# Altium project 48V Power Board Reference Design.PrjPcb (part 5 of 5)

## Sheet 48V E-Fuse.SchDoc
size 431 x 279 mm; Date: Not shown in title block; ApprovedBy: Not shown in title block; CheckedBy: Not shown in title block; Author: Not shown in title block; CompanyName: Not shown in title block; Engineer: Not shown in title block; Organization: Not shown in title block; Address1: Not shown in title block; Address2: Not shown in title block; Address3: Not shown in title block; Address4: Not shown in title block; DocumentNumber: 7; Revision: Use project parameter SCH_Rev; SheetNumber: 5; SheetTotal: 15; PageSetup: Record=PageOptions¦CenterHorizontal=True¦CenterVertical=True¦PrintScale=1.00¦XCorrection=1.00¦YCorrection=1.00¦PrintKind=0¦BorderSize=5000000¦LeftOffset=0¦BottomOffset=0¦Orientation=2¦PaperLength=1000¦PaperWidth=1000¦Scale=100¦PaperSource=15¦PrintQuality=600¦MediaType=1¦DitherType=10¦PaperKind=Letter¦PrintScaleMode=1
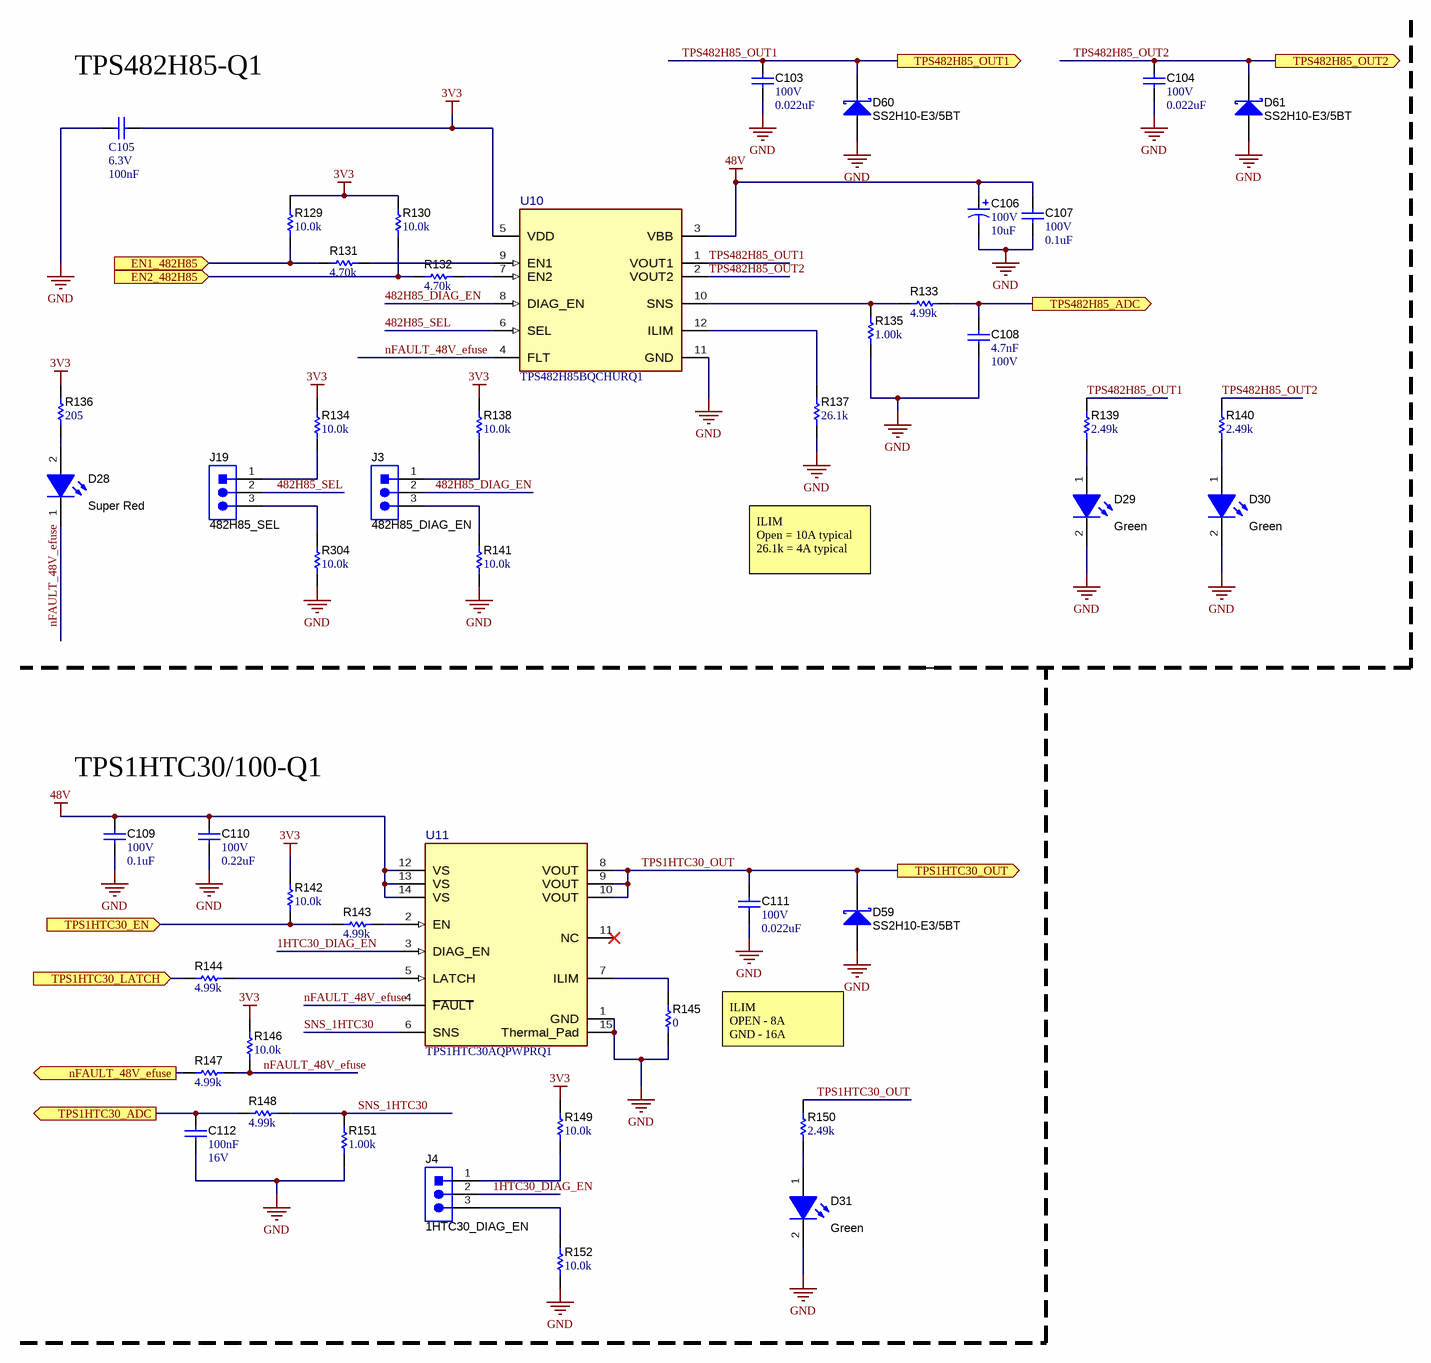
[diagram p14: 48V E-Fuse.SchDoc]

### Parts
C103  VDC_V: 100V  ValueDisplayed: 0.022uF  [1206]  (hidden comment: 12061C223JAT2A)
C104  VDC_V: 100V  ValueDisplayed: 0.022uF  [1206]  (hidden comment: 12061C223JAT2A)
C105  Cap_F: 100nF  Rated Voltage (DC): 6.3V  [WCAP-CSGP_0402_L1W0.5H0.5]  (hidden comment: 885012105001)
C106  VDC_V: 100V  ValueDisplayed: 10uF  [SM_RADIAL_E]  (hidden comment: EEE-2AA100UP)
C107  VDC_V: 100V  ValueDisplayed: 0.1uF  [1206_180]  (hidden comment: C3216X7R2A104K160AA)
C108  Cap_F: 4.7nF  VDC_V: 100V  [0603]  (hidden comment: GCM188R72A472KA37D)
C109  VDC_V: 100V  ValueDisplayed: 0.1uF  [1206]  (hidden comment: GRM319R72A104KA01D)
C110  VDC_V: 100V  ValueDisplayed: 0.22uF  [1206]  (hidden comment: C3216X7R2A224K115AA)
C111  VDC_V: 100V  ValueDisplayed: 0.022uF  [1206]  (hidden comment: 12061C223JAT2A)
C112  Cap_F: 100nF  VDC_V: 16V  [0603]  (hidden comment: GCM188R71C104KA37J)
D28  value Super Red  [WL-SMCW_RED]  (hidden comment: 150060SS75000)
D29  value Green  [LTST-C191_Green]  (hidden comment: LTST-C191KGKT)
D30  value Green  [LTST-C191_Green]  (hidden comment: LTST-C191KGKT)
D31  value Green  [LTST-C191_Green]  (hidden comment: LTST-C191KGKT)
D59  SS2H10-E3/5BT  [SMB]
D60  SS2H10-E3/5BT  [SMB]
D61  SS2H10-E3/5BT  [SMB]
J3  482H85_DIAG_EN  [TSW-103-07-G-S]
J4  1HTC30_DIAG_EN  [TSW-103-07-G-S]
J19  482H85_SEL  [TSW-103-07-G-S]
R129  ValueDisplayed: 10.0k  [0603]  (hidden comment: RNCF0603TKY10K0)
R130  ValueDisplayed: 10.0k  [0603]  (hidden comment: RNCF0603TKY10K0)
R131  ValueDisplayed: 4.70k  [0603]  (hidden comment: RC0603FR-074K7L)
R132  ValueDisplayed: 4.70k  [0603]  (hidden comment: RC0603FR-074K7L)
R133  ValueDisplayed: 4.99k  [0603]  (hidden comment: CRCW06034K99FKEAC)
R134  ValueDisplayed: 10.0k  [0603]  (hidden comment: RNCF0603TKY10K0)
R135  ValueDisplayed: 1.00k  [0603]  (hidden comment: ERA3AEB102V)
R136  ValueDisplayed: 205  [0603]  (hidden comment: RC0603FR-07205RL)
R137  ValueDisplayed: 26.1k  [0603]  (hidden comment: RC0603FR-0726K1L)
R138  ValueDisplayed: 10.0k  [0603]  (hidden comment: RNCF0603TKY10K0)
R139  ValueDisplayed: 2.49k  [0603]  (hidden comment: RC0603FR-072K49L)
R140  ValueDisplayed: 2.49k  [0603]  (hidden comment: RC0603FR-072K49L)
R141  ValueDisplayed: 10.0k  [0603]  (hidden comment: RNCF0603TKY10K0)
R142  ValueDisplayed: 10.0k  [0603]  (hidden comment: RNCF0603TKY10K0)
R143  ValueDisplayed: 4.99k  [0603]  (hidden comment: CRCW06034K99FKEAC)
R144  ValueDisplayed: 4.99k  [0603]  (hidden comment: CRCW06034K99FKEAC)
R145  ValueDisplayed: 0  [0603]  (hidden comment: ERJ-3GEY0R00V)
R146  ValueDisplayed: 10.0k  [0603]  (hidden comment: ERJ-3EKF1002V)
R147  ValueDisplayed: 4.99k  [0603]  (hidden comment: CRCW06034K99FKEAC)
R148  ValueDisplayed: 4.99k  [0603]  (hidden comment: CRCW06034K99FKEAC)
R149  ValueDisplayed: 10.0k  [0603]  (hidden comment: RNCF0603TKY10K0)
R150  ValueDisplayed: 2.49k  [0603]  (hidden comment: RC0603FR-072K49L)
R151  ValueDisplayed: 1.00k  [0603]  (hidden comment: ERJ-3EKF1001V)
R152  ValueDisplayed: 10.0k  [0603]  (hidden comment: RNCF0603TKY10K0)
R304  ValueDisplayed: 10.0k  [0603]  (hidden comment: RNCF0603TKY10K0)
U10  TPS482H85BQCHURQ1  [CHU0012A-MFG]
U11  TPS1HTC30AQPWPRQ1  [PWP0014C-MFG]

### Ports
EN1_482H85 (in), EN2_482H85 (in), nFAULT_48V_efuse (out), TPS1HTC30_ADC (out), TPS1HTC30_EN (in), TPS1HTC30_LATCH (in), TPS1HTC30_OUT (out), TPS482H85_ADC (out), TPS482H85_OUT1 (out), TPS482H85_OUT2 (out)

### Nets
3V3: C105.1 R129.2 R130.2 R134.2 R136.2 R138.2 R142.2 R146.2 R149.2 U10.5(VDD)
48V: C106.1(+) C107.1 C109.1 C110.1 U10.3(VBB) U11.12(VS) U11.13(VS) U11.14(VS)
GND: C103.2 C104.2 C105.2 C106.2(-) C107.2 C108.2 C109.2 C110.2 C111.2 C112.2 D29.2(K) D30.2(K) D31.2(K) D59.2(A) D60.2(A) D61.2(A) R135.1 R137.1 R141.1 R145.1 R151.1 R152.1 R304.1 U10.11(GND) U11.1(GND) U11.15(Thermal_Pad)
1HTC30_DIAG_EN: J4.2 U11.3(DIAG_EN)  [project net 1HTC30_DIAG_EN_5]
482H85_DIAG_EN: J3.2 U10.8(DIAG_EN)  [project net 482H85_DIAG_EN_5]
482H85_SEL: J19.2 U10.6(SEL)  [project net 482H85_SEL_5]
EN1_482H85: R129.1 R131.1 ; port EN1_482H85
EN2_482H85: R130.1 R132.1 ; port EN2_482H85
nFAULT_48V_efuse: R147.1 ; port nFAULT_48V_efuse
nFAULT_48V_efuse: D28.1(K) R146.1 R147.2 U10.4(FLT) U11.4(~{FAULT})  [project net nFAULT_48V_efuse_5]  [a separate net that carries the same name]
SNS_1HTC30: R148.2 R151.2 U11.6(SNS)  [project net SNS_1HTC30_5]
TPS1HTC30_ADC: C112.1 R148.1 ; port TPS1HTC30_ADC
TPS1HTC30_EN: R142.1 R143.1 ; port TPS1HTC30_EN
TPS1HTC30_LATCH: R144.1 ; port TPS1HTC30_LATCH
TPS1HTC30_OUT: C111.1 D59.1(K) R150.2 U11.8(VOUT) U11.9(VOUT) U11.10(VOUT) ; port TPS1HTC30_OUT
TPS482H85_ADC: C108.1 R133.2 ; port TPS482H85_ADC
TPS482H85_OUT1: C103.1 D60.1(K) R139.2 U10.1(VOUT1) ; port TPS482H85_OUT1
TPS482H85_OUT2: C104.1 D61.1(K) R140.2 U10.2(VOUT2) ; port TPS482H85_OUT2
NetD28_2: D28.2(A) R136.1
NetD29_1: D29.1(A) R139.1
NetD30_1: D30.1(A) R140.1
NetD31_1: D31.1(A) R150.1
NetJ3_1: J3.1 R138.1
NetJ3_3: J3.3 R141.2
NetJ4_1: J4.1 R149.1
NetJ4_3: J4.3 R152.2
NetJ19_1: J19.1 R134.1
NetJ19_3: J19.3 R304.2
NetR131_2: R131.2 U10.9(EN1)
NetR132_2: R132.2 U10.7(EN2)
NetR133_1: R133.1 R135.2 U10.10(SNS)
NetR137_2: R137.2 U10.12(ILIM)
NetR143_2: R143.2 U11.2(EN)
NetR144_2: R144.2 U11.5(LATCH)
NetR145_2: R145.2 U11.7(ILIM)

Not connected (* = marked no-connect by the designer): U11 11(NC)*

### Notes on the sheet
- (near C105) TPS482H85-Q1
- ILIM
  Open = 10A typical
  26.1k = 4A typical
- TPS1HTC30/100-Q1
- ILIM
  OPEN - 8A
  GND - 16A

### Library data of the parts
C103 C104 C111 = CMP-0008495-2: CAP, CERM, 0.022 uF, 100 V, +/- 5%, X7R, 1206; Manufacturer: AVX; TaMin_C: -55°C; ESR_ohm: 79m; Polarized: N; SizeAreaWB_mm2: 10.92; Value1: 0.079 ohm; U/M: EA; TaMax_C: 125°C; SizeZ_mm: 1.35; SizeX_mm: 3.2; SizeY_mm: 1.6; SizeArea_mm2: 5.12; Cap_F: 22nF; AEC Category: Q200
C105 = CMP-0115207-1: WCAP-CSGP Multilayer Ceramic Chip Capacitor, General Purpose, size 0402, X5R, 100nF, 6.3VDC; Manufacturer: Wurth Elektronik; Capacitance Tolerance: +/-20%; Dissipation Factor: 10%; Insulation Resistance: 1GOhm; Technical Reference: X5R0402104M6R3DFCT10000
C106 = CMP-0011164-2: CAP, AL, 10 uF, 100 V, +/- 20%, AEC-Q200 Grade 3, SMD; Manufacturer: Panasonic; TaMin_C: -40°C; Polarized: Y; SizeAreaWB_mm2: 118.45; Value1: Unknown; U/M: EA; Value: 10uF; TaMax_C: 85°C; SizeZ_mm: 6.2; SizeX_mm: 9.5; SizeY_mm: 8.3; Cap_Case: 8.0x6.0mm; SizeArea_mm2: 78.85; CompType: Capacitor; Cap_F: 10µF; IRMS_A: 50mA; AEC Grade: 3; AEC Category: Q200
C107 = CMP-0008709-1: CAP, CERM, 0.1 uF, 100 V, +/- 10%, X7R, 1206; Manufacturer: TDK; TaMin_C: -55°C; ESR_ohm: 0.030343; Polarized: N; SizeAreaWB_mm2: 10.92; Value1: 0.030343 ohm; U/M: EA; Value: 0.1uF; TaMax_C: 125°C; SizeZ_mm: 1.8; SizeX_mm: 3.2; SizeY_mm: 1.6; SizeArea_mm2: 5.12; Cap_F: 100nF; IRMS_A: 1.33802A; AEC Category: Q200
C108 = CMP-0079247-1: CAP, CERM, 4700 pF, 100 V,+/- 10%, X7R, AEC-Q200 Grade 1, 0603; Manufacturer: MuRata; SizeAreaWB_mm2: 4.68; SizeArea_mm2: 1.28; AEC Qualified: Y; AEC Category: Q200; Value: 4700pF; TaMax_C: 125°C; SizeZ_mm: 1; Polarized: N; TaMin_C: -55°C; SizeY_mm: 0.8; U/M: EA; SizeX_mm: 1.6
C109 = CMP-0008881-2: CAP, CERM, 0.1 uF, 100 V, +/- 10%, X7R, 1206; Manufacturer: MuRata; TaMin_C: -55°C; Polarized: N; SizeAreaWB_mm2: 10.92; Value1: Unknown; U/M: EA; Value: 0.1uF; TaMax_C: 125°C; SizeZ_mm: 1.35; SizeX_mm: 3.2; SizeY_mm: 1.6; SizeArea_mm2: 5.12; Cap_F: 100nF; AEC Category: Q200
C110 = CMP-0008713-2: CAP, CERM, 0.22 uF, 100 V, +/- 10%, X7R, 1206; Manufacturer: TDK; TaMin_C: -55°C; ESR_ohm: 14.93m; Polarized: N; SizeAreaWB_mm2: 10.92; Value1: 0.01493 ohm; U/M: EA; Value: 0.22uF; TaMax_C: 125°C; SizeZ_mm: 1.35; SizeX_mm: 3.2; SizeY_mm: 1.6; SizeArea_mm2: 5.12; Cap_F: 220nF; IRMS_A: 1.8906A; AEC Category: Q200
C112 = CMP-0007135-2: CAP, CERM, 0.1 uF, 16 V, +/- 10%, X7R, AEC-Q200 Grade 1, 0603; Manufacturer: MuRata; TaMin_C: -55°C; Polarized: N; SizeAreaWB_mm2: 4.68; Value1: Unknown; U/M: EA; Value: 0.1uF; TaMax_C: 125°C; SizeZ_mm: 1; SizeX_mm: 1.6; SizeY_mm: 0.8; SizeArea_mm2: 1.28; AEC Qualified: Y; AEC Category: Q200
D28 = CMP-0002893-1: LED, Super Red, SMD; Manufacturer: Wurth Elektronik; Io_A: 20mA; Value1: W; U/M: EA; Vf_V: 1.9V; Type: AlInGaP
D29-D31 = CMP-0078478-1: LED, Green, SMD; Manufacturer: Lite-On; Io_A: 30mA; Power_TotalModule: 75mW; Green_Lifecycle: Not Set; Vr_V: 5V; Tjmax_C: 85°C; Green_REACh: Incomplete; Value1: 0.075W; Angle: 130; Ir_A: 10µA; Vf_V: 2V; Type: AlInGaP
D59-D61 = CMP-0028987-2: Diode, Schottky, 100 V, 2 A, SMB; Manufacturer: Vishay-Semiconductor; Vf_V: 790mV; AEC Qualified: N; SizeArea_mm2: 21.336; Value: 100V; SizeX_mm: 5.6; Value1: 2A; Value2: 0.79V; SizeZ_mm: 2.6; SizeAreaWB_mm2: 44.156; AEC Category: Q101; TJmax_C: 175°C; SizeY_mm: 3.81
J3 J4 J19 = CMP-0075407-2: Header, 100mil, 3x1, Gold, TH; Manufacturer: Samtec; Pitch_mm: 2.54; Cert_VDE: N; Gender: Male; Cert_CSA: Y; Voltage_V: 550V; Green_REACh: Passed; Current_A: 6.3A; Green_Lifecycle: Active; Row_Count: 1
R129 R130 R134 R138 R141 R142 R149 R152 R304 = CMP-0023626-3: RES, 10.0 k, 0.01%, 0.063 W, 0603; Manufacturer: Stackpole Electronics Inc; Power_W: 63mW; TempCo: 5 ppm/C; Value_Code: 10k0; U/M: EA; Value: 10.0k; Res_ohm: 10k; SizeX_mm: 1.6; SizeY_mm: 0.8; SizeZ_mm: 1; Value2: 0.063W; SizeArea_mm2: 1.28; VDC_V: 50V; AEC Category: Q200
R131 R132 = CMP-0023153-5: RES, 4.70 k, 1%, 0.1 W, 0603; Manufacturer: Yageo; Power_W: 100mW; TempCo: 100 ppm/C; Value_Code: 4k70; Value: 4.70k; Res_ohm: 4.7k; SizeX_mm: 1.6; SizeY_mm: 0.8; SizeZ_mm: 1; Value2: 0.1W; SizeArea_mm2: 1.28; AEC Qualified: N; VDC_V: 75V; AEC Category: Q200; SizeAreaWB_mm2: 4.68
R133 R143 R144 R147 R148 = CMP-0082533-1: RES, 4.99 k, 1%, 0.1 W, 0603; Manufacturer: Vishay-Dale; Power_W: 100mW; TempCo: 100 ppm/C; SizeAreaWB_mm2: 4.68; Value_Code: 4k99; Value: 4.99k; EIA_Code: E96; SizeX_mm: 1.6; SizeY_mm: 0.8; SizeZ_mm: 1; Value2: 0.1W; SizeArea_mm2: 1.28; AEC Qualified: N; VDC_V: 75V; AEC Category: Q200
R135 = CMP-0078581-1: RES, 1.00 k, 0.1%, 0.1 W, AEC-Q200 Grade 0, 0603; Manufacturer: Panasonic; Power_W: 100mW; TempCo: 25 ppm/C; Value_Code: 1k00; Value: 1.00k; EIA_Code: E192; Res_ohm: 1k; SizeX_mm: 1.6; SizeY_mm: 0.8; SizeZ_mm: 1; Value2: 0.1W; SizeArea_mm2: 1.28; AEC Qualified: Y; AEC Grade: 0; AEC Category: Q200
R136 = CMP-0022904-5: RES, 205, 1%, 0.1 W, 0603; Manufacturer: Yageo; Power_W: 100mW; TempCo: 100 ppm/C; Value_Code: 205R; Value: 205; EIA_Code: E96; SizeX_mm: 1.6; SizeY_mm: 0.8; SizeZ_mm: 1; Value2: 0.1W; SizeArea_mm2: 1.28; AEC Qualified: N; VDC_V: 75V; AEC Category: Q200; SizeAreaWB_mm2: 4.68
R137 = CMP-0022957-5: RES, 26.1 k, 1%, 0.1 W, 0603; Manufacturer: Yageo; Power_W: 100mW; TempCo: 100 ppm/C; Value_Code: 26k1; Value: 26.1k; EIA_Code: E96; SizeX_mm: 1.6; SizeY_mm: 0.8; SizeZ_mm: 1; Value2: 0.1W; SizeArea_mm2: 1.28; AEC Qualified: N; VDC_V: 75V; AEC Category: Q200; SizeAreaWB_mm2: 4.68
R139 R140 R150 = CMP-0022990-5: RES, 2.49 k, 1%, 0.1 W, 0603; Manufacturer: Yageo; Power_W: 100mW; TempCo: 100 ppm/C; Value_Code: 2k49; Value: 2.49k; EIA_Code: E96; SizeX_mm: 1.6; SizeY_mm: 0.8; SizeZ_mm: 1; Value2: 0.1W; SizeArea_mm2: 1.28; AEC Qualified: N; VDC_V: 75V; AEC Category: Q200; SizeAreaWB_mm2: 4.68
R145 = CMP-0025874-4: RES, 0, 5%, 0.1 W, AEC-Q200 Grade 0, 0603; Manufacturer: Panasonic; Power_W: 100mW; TempCo: 600 ppm/C; Value_Code: 0000; Value: 0; EIA_Code: E24; SizeX_mm: 1.6; SizeY_mm: 0.8; SizeZ_mm: 1; Value2: 0.1W; SizeArea_mm2: 1.28; AEC Qualified: Y; VDC_V: 50V; AEC Category: Q200; SizeAreaWB_mm2: 4.68
R146 = CMP-0022684-2: RES, 10.0 k, 1%, 0.1 W, 0603; Manufacturer: Panasonic; Power_W: 100mW; TempCo: 100 ppm/C; Value_Code: 10k0; U/M: EA; Value: 10.0k; EIA_Code: E96; Res_ohm: 10k; SizeX_mm: 1.6; SizeY_mm: 0.8; SizeZ_mm: 1; Value2: 0.1W; SizeArea_mm2: 1.28; VDC_V: 75V; AEC Category: Q200
R151 = CMP-0022680-3: RES, 1.00 k, 1%, 0.1 W, 0603; Manufacturer: Panasonic; Power_W: 100mW; TempCo: 100 ppm/C; Value_Code: 1k00; U/M: EA; Value: 1.00k; EIA_Code: E96; Res_ohm: 1k; SizeX_mm: 1.6; SizeY_mm: 0.8; SizeZ_mm: 1; SizeArea_mm2: 1.28; VDC_V: 75V; AEC Category: Q200; Value2: 0.1W
U10 = CMP-0122244-1: 48-V, 85-mΩ Dual-Channel Smart High-Side Switch; Manufacturer: Texas Instruments; SizeZ_mm: 1mm; AEC Qualified: Yes; AEC Grade: Grade 1; Max Supply Voltage: 64V; Min Supply Voltage: 6V; Number Of Outputs: 2; Standoff Height: 0mm; TaMax_C: +125°C; TaMin_C: -40°C
U11 = CMP-0097835-1: 30-mΩ, 24-V, 6-A Single-Channel Automotive Smart High-Side Switch; Manufacturer: Texas Instruments; Min Supply Voltage: 6V; Number Of Outputs: 1; Nominal Supply Current: 0.98-1mA; TaMin_C: -40°C; TaMax_C: +125°C; SizeZ_mm: 1.2mm; AEC Grade: Grade 1; Max Supply Voltage: 48V; AEC Qualified: Yes; Standoff Height: 0.05mm

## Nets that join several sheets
3V3: LM74900-Q1 (R123.2 R124.2 R125.2), TPS1211-Q1 (R208.1 R210.1 R214.2 R215.2), TPS4HC120-Q1 (R97.2 R98.2 R104.2), TPS1214-Q1 (R35.2 R39.2 R40.2 R41.2), (BLDC) DRV8363-Q1 (5 pins), Motor Drivers (6 pins), 12V E-Fuse (9 pins), Backbone_input2 (5 pins), Power (R61.2), (SPI Expander) TXE8124-Q1 (5 pins), AM26 Connectors (J16.1), Backbone_input1 (8 pins), 48V E-Fuse (10 pins)
5V_AM26: Power (D12.1), AM26 Connectors (J17.2)
12V: LM74900-Q1 (14 pins), TPS1211-Q1 (9 pins), TPS4HC120-Q1 (C87.1 C88.1 R307.1 TP45.1), (BLDC) DRV8363-Q1 (C167.1 U16.30), Motor Drivers (7 pins), 12V E-Fuse (13 pins), Power (C70.1 D10.1 R57.2 U5.6)
48V: Top Sheet (J7.2), TPS1214-Q1 (10 pins), (BLDC) DRV8363-Q1 (23 pins), Motor Drivers (8 pins), Backbone_input2 (8 pins), Power (L4.1), Backbone_input1 (10 pins), 48V E-Fuse (8 pins)
GND: Top Sheet (10 pins), LM74900-Q1 (15 pins), TPS1211-Q1 (17 pins), TPS4HC120-Q1 (19 pins), TPS1214-Q1 (23 pins), (BLDC) DRV8363-Q1 (31 pins), Motor Drivers (45 pins), 12V E-Fuse (28 pins), Backbone_input2 (25 pins), Power (25 pins), (SPI Expander) TXE8124-Q1 (C199.2 U17.3), AM26 Connectors (6 pins), Backbone_input1 (29 pins), 48V E-Fuse (26 pins)
: (BLDC) DRV8363-Q1 (R258.1), Motor Drivers (R7.1 R17.1), 12V E-Fuse (R67.1 R86.1), (SPI Expander) TXE8124-Q1 (R294.1), AM26 Connectors (J15.80)
BUCK_PG: Power (R50.1 R61.1 U4.2 U5.1), (SPI Expander) TXE8124-Q1 (U17.22)
DIAGEN_TPS4HC120: TPS4HC120-Q1 (R94.2), (SPI Expander) TXE8124-Q1 (U17.10)
DRV8245_OUT1: Top Sheet (J8.2), Motor Drivers (C3.2 R2.2 U1.8 U1.9)
DRV8245_OUT2: Top Sheet (J8.1), Motor Drivers (C4.2 R1.2 U1.5 U1.6)
DRV8263_OUT1: Top Sheet (J9.2), Motor Drivers (C21.2 C22.1 R15.2 U2.7)
DRV8263_OUT2: Top Sheet (J9.1), Motor Drivers (C22.2 C24.2 R16.2 U2.5)
DRV8363_EBRAKE: (BLDC) DRV8363-Q1 (U16.29), (SPI Expander) TXE8124-Q1 (U17.19)
DRV8363_INHA: (BLDC) DRV8363-Q1 (U16.11), AM26 Connectors (J14.36)
DRV8363_INHB: (BLDC) DRV8363-Q1 (U16.13), AM26 Connectors (J14.34)
DRV8363_INHC: (BLDC) DRV8363-Q1 (U16.15), AM26 Connectors (J14.32)
DRV8363_INLA: (BLDC) DRV8363-Q1 (U16.12), AM26 Connectors (J14.37)
DRV8363_INLB: (BLDC) DRV8363-Q1 (U16.14), AM26 Connectors (J14.33)
DRV8363_INLC: (BLDC) DRV8363-Q1 (U16.16), AM26 Connectors (J14.31)
DRV8363_OUTA: Top Sheet (J5.1), (BLDC) DRV8363-Q1 (14 pins)
DRV8363_OUTB: Top Sheet (J5.2), (BLDC) DRV8363-Q1 (14 pins)
DRV8363_OUTC: Top Sheet (J5.3), (BLDC) DRV8363-Q1 (14 pins)
DRV8363_SOA: (BLDC) DRV8363-Q1 (C186.1 R278.1), AM26 Connectors (J13.23)
DRV8363_SOB: (BLDC) DRV8363-Q1 (C187.1 R279.1), AM26 Connectors (J13.28)
DRV8363_SOC: (BLDC) DRV8363-Q1 (C188.1 R280.1), AM26 Connectors (J13.26)
DRVOFF_DRV82xx: Motor Drivers (U1.10 U2.8), (SPI Expander) TXE8124-Q1 (U17.24)
DRVOFF_DRV8363: (BLDC) DRV8363-Q1 (U16.9), (SPI Expander) TXE8124-Q1 (U17.17)
EN1_482H85: (SPI Expander) TXE8124-Q1 (U17.12), 48V E-Fuse (R129.1 R131.1)
EN1_TPS4HC120: TPS4HC120-Q1 (R90.2), (SPI Expander) TXE8124-Q1 (U17.4)
EN2_482H85: (SPI Expander) TXE8124-Q1 (U17.13), 48V E-Fuse (R130.1 R132.1)
EN2_TPS4HC120: TPS4HC120-Q1 (R91.2), (SPI Expander) TXE8124-Q1 (U17.5)
EN3_TPS4HC120: TPS4HC120-Q1 (R92.2), (SPI Expander) TXE8124-Q1 (U17.6)
EN4_TPS4HC120: TPS4HC120-Q1 (R93.2), (SPI Expander) TXE8124-Q1 (U17.7)
EN/IN1_DRV8245: Motor Drivers (U1.11), AM26 Connectors (J14.40)
EN/IN1_DRV8263: Motor Drivers (U2.9), AM26 Connectors (J15.78)
EN_LM74900: LM74900-Q1 (R123.1 U9.6), AM26 Connectors (J18.44)
EN_TPS1214: TPS1214-Q1 (R35.1 U3.1), AM26 Connectors (J15.57)
FLT_I_TPS1211: TPS1211-Q1 (D41.1 R208.2 U14.5), AM26 Connectors (J18.43)
FLT_T_TPS1211: TPS1211-Q1 (D42.1 R210.2 U14.4), AM26 Connectors (J13.7)
IDIR_TPS1212_input1: AM26 Connectors (J15.51), Backbone_input1 (R181.1)
IDIR_TPS1212_input2: Backbone_input2 (R242.1), AM26 Connectors (J14.13)
IMON_LM74900: LM74900-Q1 (R126.2 U9.10), AM26 Connectors (J18.69)
IMON_TPS1211: TPS1211-Q1 (R211.2 TP22.1 U14.7), AM26 Connectors (J18.67)
IMON_TPS1212_input1: AM26 Connectors (J13.29), Backbone_input1 (5 pins)
IMON_TPS1212_input2: Backbone_input2 (C161.1 R252.2 TP28.1 U15.9), AM26 Connectors (J13.25)
IMON_TPS1214: TPS1214-Q1 (C57.1 R45.2 TP7.1 U3.9), AM26 Connectors (J13.24)
INP_G_TPS1211: TPS1211-Q1 (U14.2), AM26 Connectors (J14.15)
INP_TPS1211: TPS1211-Q1 (U14.3), AM26 Connectors (J14.14)
INP_TPS1212_input1: AM26 Connectors (J15.52), Backbone_input1 (R176.1 U13.4)
INP_TPS1212_input2: Backbone_input2 (R237.1), AM26 Connectors (J14.18)
INP_TPS1214: TPS1214-Q1 (U3.3), AM26 Connectors (J15.53)
IPROPI_DRV8245: Motor Drivers (C6.1 R5.2), AM26 Connectors (J18.63)
IPROPI_DRV8263: Motor Drivers (C25.1 R12.2), AM26 Connectors (J18.46)
ITMPO_TPS1212_input1: AM26 Connectors (J13.27), Backbone_input1 (C130.1 R188.2 U12.10)
ITMPO_TPS1212_input2: Backbone_input2 (C159.1 R249.2 U15.10), AM26 Connectors (J13.6)
ITMPO_TPS1214: TPS1214-Q1 (C56.1 R42.2 U3.10), AM26 Connectors (J13.2)
LHI_TPS2HCS05: 12V E-Fuse (R74.2), (SPI Expander) TXE8124-Q1 (U17.15)
LHI_TPS2HCS10: 12V E-Fuse (R80.2), (SPI Expander) TXE8124-Q1 (U17.26)
nCS_DRV8245: Motor Drivers (R6.2 R9.1), AM26 Connectors (J18.45)
nCS_DRV8263: Motor Drivers (R18.2 R20.1), AM26 Connectors (J18.50)
nCS_DRV8363: (BLDC) DRV8363-Q1 (R257.2 R260.1), AM26 Connectors (J18.49)
nCS_TPS2HCS05: 12V E-Fuse (R66.1 R72.1), AM26 Connectors (J13.9)
nCS_TPS2HCS10: 12V E-Fuse (R88.2 R89.1), AM26 Connectors (J14.19)
nCS_TXE8124: (SPI Expander) TXE8124-Q1 (R291.2 R296.1), AM26 Connectors (J15.71)
nFAULT_48V_efuse: AM26 Connectors (J14.38), 48V E-Fuse (R147.1)
nFAULT_1214: TPS1214-Q1 (D9.1 R40.1 U3.6), AM26 Connectors (J15.58)
nFAULT_DRV82xx: Motor Drivers (D3.1 R4.1 U1.1 U2.1), AM26 Connectors (J13.8)
nFAULT_DRV8363: (BLDC) DRV8363-Q1 (D50.1 R262.1 U16.22), (SPI Expander) TXE8124-Q1 (U17.16)
nFAULT_LM74900: LM74900-Q1 (R125.1 U9.12), AM26 Connectors (J18.48)
nFAULT_TPS4HC120: TPS4HC120-Q1 (R99.2), (SPI Expander) TXE8124-Q1 (U17.11)
nFLT_LM686x5: Power (R49.1 U4.8), (SPI Expander) TXE8124-Q1 (U17.14)
nFLT_TPS2HCS10/05: 12V E-Fuse (R84.1), (SPI Expander) TXE8124-Q1 (U17.25)
nFLT_TPS1212_input1: AM26 Connectors (J15.73), Backbone_input1 (R185.2)
nFLT_TPS1212_input2: Backbone_input2 (R246.2), AM26 Connectors (J14.12)
nINT_TXE8124: (SPI Expander) TXE8124-Q1 (R290.2 U17.32), AM26 Connectors (J15.55)
nLPM_TPS4HC120: TPS4HC120-Q1 (R100.2), (SPI Expander) TXE8124-Q1 (U17.27)
nLPM_TPS1212_input1: AM26 Connectors (J15.75), Backbone_input1 (Q13.1 R178.1)
nLPM_TPS1212_input2: Backbone_input2 (Q22.1 R239.1), AM26 Connectors (J14.17)
nLPM_TPS1214: TPS1214-Q1 (U3.2), AM26 Connectors (J15.74)
nSLEEP_DRV82xx: Motor Drivers (U1.3 U2.3), (SPI Expander) TXE8124-Q1 (U17.23)
nSLEEP_DRV8363: (BLDC) DRV8363-Q1 (U16.21), (SPI Expander) TXE8124-Q1 (U17.18)
nSLEEP_LM74900: LM74900-Q1 (R124.1 U9.7), (SPI Expander) TXE8124-Q1 (U17.21)
OUT1_TPS4HC120: Top Sheet (J12.4), TPS4HC120-Q1 (5 pins)
OUT2_TPS4HC120: Top Sheet (J12.3), TPS4HC120-Q1 (5 pins)
OUT3_TPS4HC120: Top Sheet (J12.2), TPS4HC120-Q1 (5 pins)
OUT4_TPS4HC120: Top Sheet (J12.1), TPS4HC120-Q1 (5 pins)
PH/IN2_DRV8245: Motor Drivers (U1.12), AM26 Connectors (J14.39)
PH/IN2_DRV8263: Motor Drivers (U2.10), AM26 Connectors (J15.77)
RESET_TXE8124: (SPI Expander) TXE8124-Q1 (R292.2 U17.31), AM26 Connectors (J15.54)
SCLK: (BLDC) DRV8363-Q1 (R256.1), Motor Drivers (R10.1 R13.1), 12V E-Fuse (R65.1 R83.1), (SPI Expander) TXE8124-Q1 (R293.1), AM26 Connectors (J15.79)
SCP_TEST_TPS1214: TPS1214-Q1 (U3.4), AM26 Connectors (J15.59)
SDO: (BLDC) DRV8363-Q1 (R259.1), Motor Drivers (R11.1 R19.1), 12V E-Fuse (R68.1 R87.1), (SPI Expander) TXE8124-Q1 (R295.1), AM26 Connectors (J14.35)
SEL0_TPS4HC120: TPS4HC120-Q1 (R95.2), (SPI Expander) TXE8124-Q1 (U17.8)
SEL1_TPS4HC120: TPS4HC120-Q1 (R96.2), (SPI Expander) TXE8124-Q1 (U17.9)
SNS_TPS2HCS05: 12V E-Fuse (C79.1 R73.2 U6.3), AM26 Connectors (J18.65)
SNS_TPS2HCS10: 12V E-Fuse (C85.1 R85.2 U7.2), AM26 Connectors (J18.66)
SNS_TPS4HC120: TPS4HC120-Q1 (R101.2), AM26 Connectors (J18.64)
TPLD_LATCH_RST: AM26 Connectors (J18.47), Backbone_input1 (U13.1)
TPS1HTC30_ADC: AM26 Connectors (J18.68), 48V E-Fuse (C112.1 R148.1)
TPS1HTC30_EN: (SPI Expander) TXE8124-Q1 (U17.20), 48V E-Fuse (R142.1 R143.1)
TPS1HTC30_LATCH: AM26 Connectors (J13.5), 48V E-Fuse (R144.1)
TPS1HTC30_OUT: Top Sheet (J7.1), 48V E-Fuse (6 pins)
TPS482H85_ADC: AM26 Connectors (J18.42), 48V E-Fuse (C108.1 R133.2)
TPS482H85_OUT1: Top Sheet (J6.1), 48V E-Fuse (C103.1 D60.1 R139.2 U10.1)
TPS482H85_OUT2: Top Sheet (J6.2), 48V E-Fuse (C104.1 D61.1 R140.2 U10.2)
VOUT1_TPS2HCS05: Top Sheet (J10.1), 12V E-Fuse (5 pins)
VOUT1_TPS2HCS10: Top Sheet (J11.1), 12V E-Fuse (6 pins)
VOUT2_TPS2HCS05: Top Sheet (J10.2), 12V E-Fuse (5 pins)
VOUT2_TPS2HCS10: Top Sheet (J11.2), 12V E-Fuse (6 pins)
VOUT_TPS1211: Top Sheet (T9.1), TPS1211-Q1 (13 pins)
VOUT_TPS1214: Top Sheet (T8.1), TPS1214-Q1 (15 pins)
VS_ORing: Backbone_input2 (D43.1 R227.2 TP49.1), Backbone_input1 (D32.1 D33.1 R166.2 TP47.1)
WAKE_TPS1212_input1: AM26 Connectors (J15.76), Backbone_input1 (R187.2)
WAKE_TPS1212_input2: Backbone_input2 (R248.2), AM26 Connectors (J14.11)
WAKE_TPS1214: TPS1214-Q1 (C54.1 R41.1 U3.5), AM26 Connectors (J15.72)

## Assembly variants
001: not fitted C3 C4 C5 C6 C21 C22 C24 C25 C26 C100 C101 C102 C103 C106 C113 C119 C121 C122 C123 C123 C124 C125 C128 C129 C130 C131 C132 C151 C154 C155 C156 C168 C171 C175 C177 C185 C195 C196 C200 C201 C206 C207 C208 C209 C213 C214 C215 C216 C? C? C? C? D53 D54 D55 D56 D57 D58 D59 D62 D63 D? D? D? D? R66 R74 R105 R106 R145 R154 R154 R159 R160 R174 R176 R178 R183 R190 R192 R210 R217 R220 R222 R232 R233 R238 R246 R298 R301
